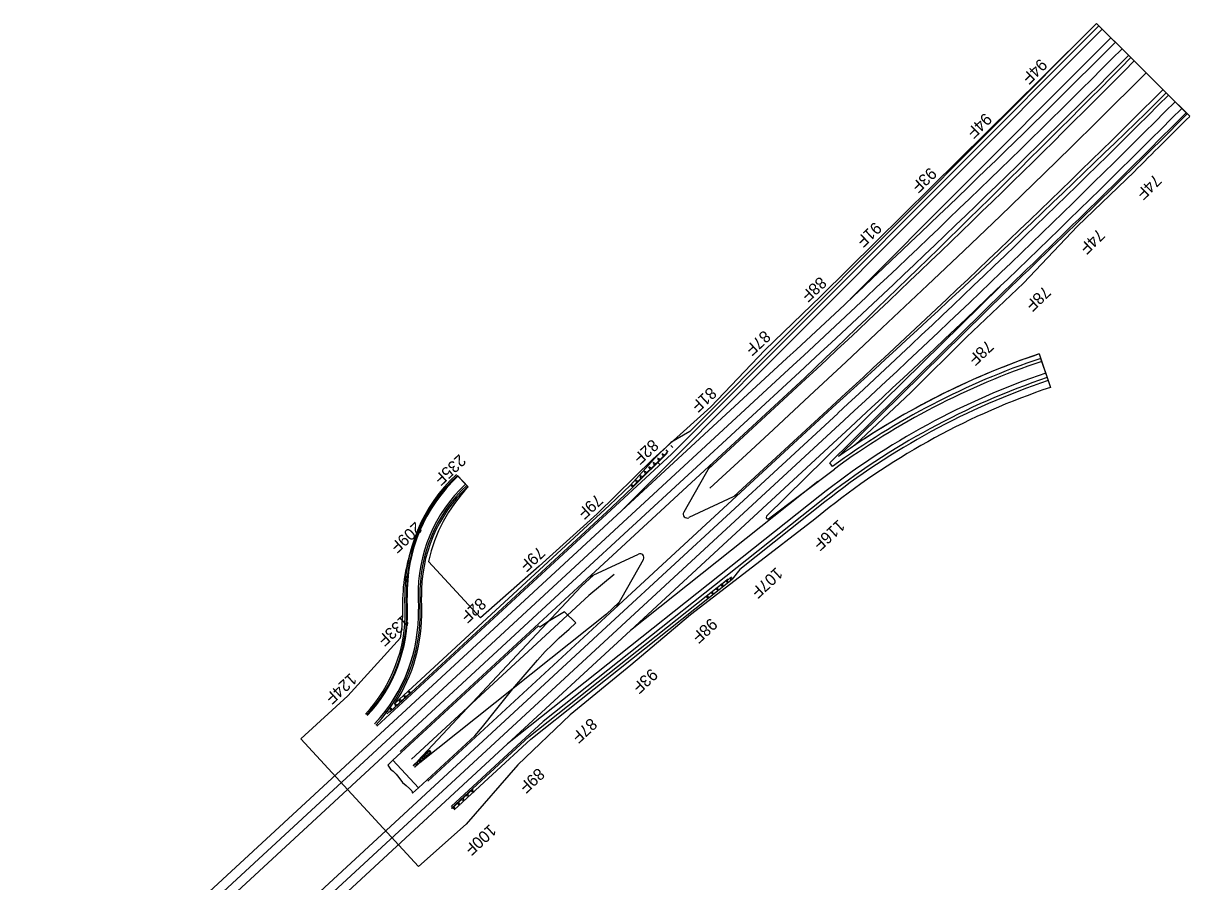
# Model space of a CAD drawing. Extents: x 2163396 to 2173129, y 605545 to 614595.
# Drawn here: x 2171635 to 2173129, y 613496 to 614595 of the extents above; entities that cross this region are included whole.
import ezdxf

# ---------------------------------------------------------------- set-up
doc = ezdxf.new("R2010")
doc.units = 0
for name, color, linetype in [('RD_PD_AsphRem', 7, 'Continuous'), ('RD_PD_CstnLmt', 7, 'Continuous'), ('RD_PD_EarthShd', 7, 'Continuous'), ('RD_PD_Final_LnLine', 7, 'Continuous'), ('RD_PD_Final_TrvlWay', 7, 'Continuous'), ('RD_PD_GR', 7, 'Continuous'), ('RD_PD_MedBWall', 7, 'Continuous'), ('RD_PD_MedGR', 7, 'Continuous'), ('RD_PD_TX_CstnLmt', 7, 'Continuous')]:
    doc.layers.add(name, color=color, linetype=linetype)

msp = doc.modelspace()

# ---------------------------------------------------------------- linework, layer by layer
at = {"layer": 'RD_PD_AsphRem'}
for p, q in [((2172295.2, 613823.7), (2172108.7, 613651.4)), ((2172213.5, 613682.8), (2172223.3, 613694.5)), ((2172141.3, 613616.1), (2172213.5, 613682.8)), ((2172108.7, 613651.4), (2172102.2, 613645.4)), ((2172102.2, 613645.4), (2172103.2, 613643.8)), ((2172108.7, 613651.4), (2172141.3, 613616.1)), ((2172141.3, 613616.1), (2172108.7, 613651.4)), ((2172133.9, 613609.3), (2172141.3, 613616.1))]:
    msp.add_line(p, q, dxfattribs=at)
for points in [[(2172223.3, 613694.5), (2172240.1, 613715.1), (2172262.5, 613742.8), (2172280.8, 613764.4), (2172294, 613779.7), (2172303.5, 613790.6), (2172312.5, 613799.5), (2172321.5, 613808.2), (2172334.3, 613819.4), (2172343, 613827.4), (2172339.4, 613831), (2172332.1, 613838.1), (2172328.5, 613841.6), (2172309.1, 613830.2), (2172296.9, 613821.9), (2172295.2, 613823.7)], [(2172103.2, 613643.8), (2172105.8, 613640.2), (2172109.2, 613637.5), (2172112.9, 613633.8), (2172116.4, 613629.4), (2172121.1, 613623.2), (2172125.8, 613619.1), (2172129.9, 613615.1), (2172132.9, 613612.2), (2172133.9, 613609.3)]]:
    msp.add_lwpolyline(points, dxfattribs=at)
at = {"layer": 'RD_PD_CstnLmt'}
for p, q in [((2173009.8, 614595.3), (2172939.6, 614525)), ((2173053.9, 614551.4), (2173009.8, 614595.3)), ((2173099.2, 614506.1), (2173053.9, 614551.4)), ((2172939.6, 614525), (2172868.8, 614455.3)), ((2173129.2, 614476.2), (2173099.2, 614506.1)), ((2172868.8, 614455.3), (2172798.1, 614385.6)), ((2173057.9, 614405.3), (2172985.6, 614335.5)), ((2172798.1, 614385.6), (2172727.4, 614315.6)), ((2172985.6, 614335.5), (2172916.4, 614262.5)), ((2172727.4, 614315.6), (2172656.9, 614245.7)), ((2172916.4, 614262.5), (2172843.4, 614193.3)), ((2172656.9, 614245.7), (2172585.1, 614176.8)), ((2172843.4, 614193.3), (2172772, 614122.4)), ((2172585.1, 614176.8), (2172515.9, 614104.3)), ((2172936.4, 614171.9), (2172950.9, 614129)), ((2172772, 614122.4), (2172700.9, 614055.5)), ((2172515.9, 614104.3), (2172441.6, 614037.3)), ((2172441.6, 614037.3), (2172370.3, 613967.2)), ((2172205.1, 614001.5), (2172191.3, 614016.2)), ((2172667.6, 613975.1), (2172649.1, 613960.1)), ((2172370.3, 613967.2), (2172296.2, 613900)), ((2172649.1, 613960.1), (2172569.4, 613899)), ((2172220.9, 613834.1), (2172154.4, 613906.2)), ((2172296.2, 613900), (2172220.9, 613834.1)), ((2172569.4, 613899), (2172489.8, 613837.7)), ((2172121.3, 613845.8), (2172121.2, 613848.3)), ((2172489.8, 613837.7), (2172413.3, 613773.2)), ((2172118.4, 613808.3), (2172051, 613733.9)), ((2172413.3, 613773.2), (2172335.8, 613709.8)), ((2172051, 613733.9), (2171990.6, 613678.8)), ((2172335.8, 613709.8), (2172268.5, 613645.8)), ((2172141.5, 613515.5), (2171990.6, 613678.8)), ((2172268.5, 613645.8), (2172202.6, 613569.7)), ((2172202.6, 613569.7), (2172141.5, 613515.5))]:
    msp.add_line(p, q, dxfattribs=at)
for centre, radius, start, end in [((2162936.5, 624645.9), 14398.4, 314.66467, 315.06467), ((2173249.3, 613242.2), 980.9, 108.5981, 123.9911), ((2173249.3, 613242.2), 935.7, 108.5981, 128.4389), ((2172335.8, 613861), 212, 132.9512, 161.6696), ((2172349.8, 613863.5), 200, 136.3428, 167.6655), ((2172333.1, 613853.5), 212, 159.524, 181.4209), ((2171933.4, 613841.2), 187.9, 349.929, 1.4209)]:
    msp.add_arc(centre, radius, start, end, dxfattribs=at)
at = {"layer": 'RD_PD_EarthShd'}
for p, q in [((2173010, 614595.1), (2172489, 614072.7)), ((2172893.3, 614251.2), (2172679.3, 614040.5)), ((2172637.7, 614139.9), (2172512.6, 614024.4)), ((2172670.3, 614104.7), (2172545.2, 613989.1)), ((2172489, 614072.7), (2172464.8, 614058.4)), ((2172443.5, 614037.4), (2172464.8, 614058.4)), ((2172443.5, 614037.4), (2172413.2, 614004)), ((2172386.2, 613978.1), (2172413.2, 614004)), ((2172111.2, 613724.2), (2172386.2, 613978.1)), ((2172661.8, 613982.3), (2172552.9, 613895.8)), ((2172365.7, 613888.7), (2172349.7, 613873.9)), ((2172552.9, 613895.8), (2172543.4, 613883.6)), ((2172349.7, 613873.9), (2172140.7, 613650.6)), ((2172285.2, 613678.6), (2172543.4, 613883.6)), ((2172124.4, 613844.7), (2172124, 613860)), ((2172145.7, 613845.3), (2172145.4, 613860.6)), ((2172398.2, 613853.4), (2172382.2, 613838.7)), ((2172382.2, 613838.7), (2172143, 613648.1)), ((2172187.1, 613588), (2172285.2, 613678.6))]:
    msp.add_line(p, q, dxfattribs=at)
for centre, radius, start, end in [((2162901.4, 624611.9), 14298.9, 312.91522, 315.26045), ((2162971.9, 624679.6), 14348.9, 312.52438, 314.86961), ((2162936.5, 624645.9), 14394, 313.76687, 315.06467), ((2173249.3, 613242.2), 980.9, 108.5981, 125.5268), ((2173249.3, 613242.2), 944.9, 108.5981, 128.4389), ((2172333, 613865.2), 209, 133.1773, 181.4209), ((2172333, 613865.2), 187.7, 133.1773, 181.4209), ((2171934.5, 613840), 190, 317.0978, 1.4209), ((2171934.5, 613840), 211.3, 326.756, 1.4209)]:
    msp.add_arc(centre, radius, start, end, dxfattribs=at)
at = {"layer": 'RD_PD_Final_LnLine'}
for p, q in [((2173017.1, 614588), (2172401.6, 613970.8)), ((2173028.4, 614576.7), (2172994.5, 614542.8)), ((2173034, 614571.1), (2173000.1, 614537.2)), ((2172994.5, 614542.8), (2172694.5, 614241.9)), ((2172886.3, 614258.4), (2172587.2, 613963.9)), ((2172621.5, 614157.6), (2172336.2, 613894.2)), ((2172401.6, 613970.8), (2172613.3, 614166.4)), ((2172629.6, 614148.7), (2172344.4, 613885.4)), ((2172678.5, 614095.8), (2172393.2, 613832.5)), ((2172686.6, 614087), (2172401.4, 613823.6)), ((2172694.7, 614078.2), (2172412.8, 613817.8)), ((2172515.9, 614030.1), (2172481.2, 613969.2)), ((2172589.8, 613960.9), (2172674.1, 614024.4)), ((2172201.6, 614005.2), (2172192, 614015.4)), ((2172653, 614008.5), (2172412.8, 613817.8)), ((2172655.6, 613990.2), (2172255.3, 613672.4)), ((2172551.1, 613991.9), (2172487.6, 613962.2)), ((2172401.6, 613970.8), (2172328.1, 613903)), ((2172359.7, 613885.9), (2172423.2, 613915.6)), ((2172328.1, 613903), (2171635.3, 613263.3)), ((2172394.9, 613847.7), (2172429.6, 613908.6)), ((2172336.2, 613894.2), (2171643.5, 613254.5)), ((2172344.4, 613885.4), (2171651.6, 613245.7)), ((2172127.4, 613844.8), (2172127, 613860.1)), ((2172141, 613860.5), (2172141.4, 613845.1)), ((2172393.2, 613832.5), (2171700.5, 613192.8)), ((2172401.4, 613823.6), (2171708.6, 613184)), ((2172412.8, 613817.8), (2172255.3, 613672.4)), ((2172085.3, 613698.3), (2172085.7, 613698.7)), ((2172255.3, 613672.4), (2171716.8, 613175.1))]:
    msp.add_line(p, q, dxfattribs=at)
for centre, radius, start, end in [((2162936.5, 624645.9), 14276, 312.71947, 315.06467), ((2162936.5, 624645.9), 14288, 312.71947, 315.06467), ((2162936.5, 624645.9), 14264, 312.71947, 314.87186), ((2162936.5, 624645.9), 14359.9, 312.71947, 315.06467), ((2162936.5, 624645.9), 14372, 312.71947, 315.06467), ((2162936.5, 624645.9), 14384, 312.71947, 315.06467), ((2173249.3, 613242.2), 970.9, 108.5981, 126.3296), ((2173249.3, 613242.2), 954.9, 108.5981, 128.4389), ((2172333, 613865.2), 206, 133.1773, 181.4209), ((2172333, 613865.2), 192, 133.1773, 181.4209), ((2172485.5, 613966.7), 5, 150.3526, 295.0863), ((2172588.6, 613962.5), 2, 134.5538, 306.9981), ((2172425.3, 613911.1), 5, 330.3526, 115.0863), ((2171934.5, 613840), 193, 317.0978, 1.4209), ((2171934.5, 613840), 207, 316.9344, 1.4209)]:
    msp.add_arc(centre, radius, start, end, dxfattribs=at)
at = {"layer": 'RD_PD_Final_TrvlWay'}
for p, q in [((2173012.8, 614592.3), (2172466, 614044)), ((2173053.9, 614551.4), (2173012.8, 614592.3)), ((2173124.7, 614480.7), (2173099.2, 614506.1)), ((2172891.9, 614252.7), (2172668.2, 614032.4)), ((2172938.3, 614166.2), (2172946.6, 614141.6)), ((2172636.4, 614141.4), (2172351.2, 613878)), ((2172671.7, 614103.2), (2172386.4, 613839.8)), ((2172466, 614044), (2172321.3, 613910.3)), ((2172671.7, 614027.6), (2172668.2, 614032.4)), ((2172659.3, 613985.5), (2172301.1, 613701.2)), ((2172321.3, 613910.3), (2172088.2, 613695.1)), ((2172351.2, 613878), (2172118.1, 613662.8)), ((2172386.4, 613839.8), (2172153.3, 613624.6)), ((2172301.1, 613701.2), (2172183.2, 613592.3))]:
    msp.add_line(p, q, dxfattribs=at)
for centre, radius, start, end in [((2157810.5, 629656.7), 21460, 313.69841, 315.26061), ((2163043.2, 624746.4), 14352.2, 312.13429, 314.47973), ((2162936.5, 624645.9), 14392, 313.76687, 315.06467), ((2173249.3, 613242.2), 974.9, 108.5981, 126.3296), ((2173249.3, 613242.2), 948.9, 108.5981, 128.4389)]:
    msp.add_arc(centre, radius, start, end, dxfattribs=at)
at = {"layer": 'RD_PD_GR'}
for p, q in [((2172461.4, 614046.2), (2172458.8, 614048.9)), ((2172467.1, 614051.9), (2172464.5, 614054.5)), ((2172458.9, 614044.5), (2172415.4, 614001.7)), ((2172415.8, 614001.3), (2172460, 614044.8)), ((2172448.6, 614038.9), (2172447.4, 614037.7)), ((2172448.9, 614037.4), (2172448, 614038.3)), ((2172448.2, 614036.8), (2172449.5, 614038)), ((2172449.6, 614035.4), (2172448.2, 614036.8)), ((2172449.5, 614038), (2172450.9, 614036.6)), ((2172450.9, 614036.6), (2172449.6, 614035.4)), ((2172454.3, 614044.5), (2172453.1, 614043.3)), ((2172454.6, 614043), (2172453.7, 614043.9)), ((2172453.9, 614042.4), (2172455.2, 614043.6)), ((2172455.3, 614041), (2172453.9, 614042.4)), ((2172455.2, 614043.6), (2172456.6, 614042.2)), ((2172456.6, 614042.2), (2172455.3, 614041)), ((2172459.3, 614045.6), (2172458.6, 614044.9)), ((2172458.6, 614044.9), (2172458.9, 614044.5)), ((2172460, 614044.8), (2172459.3, 614045.6)), ((2172431.5, 614022.1), (2172430.3, 614020.9)), ((2172431.8, 614020.6), (2172430.9, 614021.5)), ((2172431.1, 614020), (2172432.4, 614021.2)), ((2172432.5, 614018.5), (2172431.1, 614020)), ((2172432.4, 614021.2), (2172433.8, 614019.8)), ((2172433.8, 614019.8), (2172432.5, 614018.5)), ((2172437.2, 614027.7), (2172436, 614026.5)), ((2172437.5, 614026.2), (2172436.6, 614027.1)), ((2172436.8, 614025.6), (2172438.1, 614026.8)), ((2172438.2, 614024.2), (2172436.8, 614025.6)), ((2172438.1, 614026.8), (2172439.5, 614025.4)), ((2172439.5, 614025.4), (2172438.2, 614024.2)), ((2172442.9, 614033.3), (2172441.7, 614032.1)), ((2172443.2, 614031.8), (2172442.3, 614032.7)), ((2172442.5, 614031.2), (2172443.8, 614032.4)), ((2172443.9, 614029.8), (2172442.5, 614031.2)), ((2172443.8, 614032.4), (2172445.2, 614031)), ((2172445.2, 614031), (2172443.9, 614029.8)), ((2172450.5, 614030.2), (2172447.9, 614032.9)), ((2172414.4, 614005.2), (2172413.2, 614004)), ((2172414.7, 614003.7), (2172413.8, 614004.6)), ((2172414, 614003.1), (2172415.3, 614004.3)), ((2172415.3, 614004.3), (2172416.7, 614002.9)), ((2172420.1, 614010.9), (2172418.9, 614009.6)), ((2172420.4, 614009.3), (2172419.5, 614010.2)), ((2172419.7, 614008.7), (2172421, 614010)), ((2172421.1, 614007.3), (2172419.7, 614008.7)), ((2172421, 614010), (2172422.4, 614008.5)), ((2172422.4, 614008.5), (2172421.1, 614007.3)), ((2172425.8, 614016.5), (2172424.6, 614015.2)), ((2172426.1, 614015), (2172425.2, 614015.9)), ((2172425.4, 614014.3), (2172426.7, 614015.6)), ((2172426.8, 614012.9), (2172425.4, 614014.3)), ((2172426.7, 614015.6), (2172428.1, 614014.2)), ((2172428.1, 614014.2), (2172426.8, 614012.9)), ((2172388.8, 613975.4), (2172415.8, 614001.3)), ((2172415.4, 614001.7), (2172414, 614003.1)), ((2172416.7, 614002.9), (2172415.4, 614001.7)), ((2172415.4, 614001.7), (2172415.8, 614001.3)), ((2172131.6, 613737.9), (2172388.8, 613975.4)), ((2172392, 613889.6), (2172359.8, 613862.5)), ((2172539.5, 613885.3), (2172541.9, 613882.3)), ((2172541.1, 613886.5), (2172543.4, 613883.6)), ((2172509.8, 613861.6), (2172538, 613884)), ((2172537.5, 613883), (2172510.1, 613861.3)), ((2172524, 613872.3), (2172522.6, 613871.2)), ((2172522.6, 613871.2), (2172523.9, 613869.6)), ((2172523.9, 613869.6), (2172525.2, 613870.7)), ((2172525.2, 613870.7), (2172524, 613872.3)), ((2172524.5, 613870.2), (2172525.3, 613869.2)), ((2172526, 613869.7), (2172524.6, 613868.7)), ((2172530.3, 613877.3), (2172528.9, 613876.2)), ((2172528.9, 613876.2), (2172530.1, 613874.6)), ((2172530.1, 613874.6), (2172531.5, 613875.7)), ((2172531.5, 613875.7), (2172530.3, 613877.3)), ((2172530.8, 613875.2), (2172531.6, 613874.2)), ((2172532.3, 613874.7), (2172530.9, 613873.6)), ((2172536.5, 613882.2), (2172535.2, 613881.1)), ((2172535.2, 613881.1), (2172536.4, 613879.6)), ((2172536.4, 613879.6), (2172537.8, 613880.7)), ((2172537.8, 613880.7), (2172536.5, 613882.2)), ((2172537.1, 613880.1), (2172537.9, 613879.1)), ((2172538.5, 613879.7), (2172537.2, 613878.6)), ((2172537.8, 613882.6), (2172537.5, 613883)), ((2172538.6, 613883.2), (2172537.8, 613882.6)), ((2172538, 613884), (2172538.6, 613883.2)), ((2172359.8, 613862.5), (2172132.6, 613652.7)), ((2172282.8, 613681.5), (2172509.8, 613861.6)), ((2172510.1, 613861.3), (2172509.8, 613861.6)), ((2172511.5, 613862.3), (2172510.1, 613861.3)), ((2172510.1, 613861.3), (2172511.3, 613859.7)), ((2172511.3, 613859.7), (2172512.7, 613860.8)), ((2172512.7, 613860.8), (2172511.5, 613862.3)), ((2172512, 613860.2), (2172512.8, 613859.3)), ((2172513.5, 613859.8), (2172512.1, 613858.7)), ((2172517.7, 613867.3), (2172516.4, 613866.2)), ((2172516.4, 613866.2), (2172517.6, 613864.7)), ((2172517.6, 613864.7), (2172519, 613865.7)), ((2172519, 613865.7), (2172517.7, 613867.3)), ((2172518.3, 613865.2), (2172519.1, 613864.2)), ((2172519.7, 613864.8), (2172518.4, 613863.7)), ((2172131.6, 613737.9), (2172105.2, 613713.5)), ((2172105.6, 613714.5), (2172131.3, 613738.3)), ((2172121.9, 613734), (2172123.2, 613735.2)), ((2172127.8, 613739.5), (2172129.1, 613740.7)), ((2172129.3, 613739.1), (2172128.4, 613740.1)), ((2172129.9, 613739.7), (2172128.6, 613738.6)), ((2172128.6, 613738.6), (2172130, 613737.1)), ((2172131.3, 613738.3), (2172129.9, 613739.7)), ((2172130, 613737.1), (2172131.3, 613738.3)), ((2172131.3, 613738.3), (2172131.6, 613737.9)), ((2172110.2, 613723.2), (2172111.4, 613724.4)), ((2172111.7, 613722.9), (2172110.8, 613723.8)), ((2172112.3, 613723.5), (2172111, 613722.3)), ((2172111, 613722.3), (2172112.4, 613720.8)), ((2172113.7, 613722), (2172112.3, 613723.5)), ((2172112.4, 613720.8), (2172113.7, 613722)), ((2172116, 613728.6), (2172117.3, 613729.8)), ((2172117.5, 613728.3), (2172116.7, 613729.2)), ((2172118.2, 613728.9), (2172116.9, 613727.7)), ((2172116.9, 613727.7), (2172118.2, 613726.2)), ((2172119.5, 613727.4), (2172118.2, 613728.9)), ((2172118.2, 613726.2), (2172119.5, 613727.4)), ((2172123.4, 613733.7), (2172122.6, 613734.6)), ((2172124.1, 613734.3), (2172122.8, 613733.1)), ((2172122.8, 613733.1), (2172124.1, 613731.7)), ((2172125.4, 613732.8), (2172124.1, 613734.3)), ((2172124.1, 613731.7), (2172125.4, 613732.8)), ((2172102.2, 613710.8), (2172099.7, 613713.5)), ((2172103.7, 613712.1), (2172101.2, 613714.9)), ((2172104.3, 613717.8), (2172105.6, 613719)), ((2172104.5, 613714.2), (2172105.2, 613714.9)), ((2172105.2, 613713.5), (2172104.5, 613714.2)), ((2172105.8, 613717.4), (2172104.9, 613718.4)), ((2172106.4, 613718), (2172105.1, 613716.8)), ((2172105.1, 613716.8), (2172106.5, 613715.4)), ((2172105.2, 613714.9), (2172105.6, 613714.5)), ((2172107.8, 613716.6), (2172106.4, 613718)), ((2172106.5, 613715.4), (2172107.8, 613716.6)), ((2172211, 613615.2), (2172282.8, 613681.5)), ((2172211, 613615.2), (2172183.8, 613590.1)), ((2172184.2, 613589.7), (2172211.3, 613614.8)), ((2172197, 613601.6), (2172198.3, 613602.8)), ((2172198.4, 613600.1), (2172197, 613601.6)), ((2172198.3, 613602.8), (2172199.6, 613601.3)), ((2172199.6, 613601.3), (2172198.4, 613600.1)), ((2172199, 613600.7), (2172199.8, 613599.8)), ((2172199.2, 613599.2), (2172200.5, 613600.4)), ((2172202.9, 613607), (2172204.2, 613608.2)), ((2172204.2, 613605.5), (2172202.9, 613607)), ((2172204.2, 613608.2), (2172205.5, 613606.7)), ((2172205.5, 613606.7), (2172204.2, 613605.5)), ((2172204.9, 613606.1), (2172205.7, 613605.2)), ((2172205.1, 613604.6), (2172206.4, 613605.8)), ((2172208.8, 613612.4), (2172210, 613613.6)), ((2172210.1, 613611), (2172208.8, 613612.4)), ((2172210, 613613.6), (2172211.4, 613612.2)), ((2172211.4, 613612.2), (2172210.1, 613611)), ((2172210.8, 613611.6), (2172211.6, 613610.7)), ((2172211.3, 613614.8), (2172211, 613615.2)), ((2172211, 613610.1), (2172212.2, 613611.2)), ((2172183.8, 613590.1), (2172184.2, 613589.7)), ((2172185.2, 613590.7), (2172186.5, 613591.9)), ((2172186.6, 613589.3), (2172185.2, 613590.7)), ((2172186.5, 613591.9), (2172187.9, 613590.5)), ((2172187.9, 613590.5), (2172186.6, 613589.3)), ((2172187.2, 613589.9), (2172188.1, 613588.9)), ((2172187.4, 613588.3), (2172188.7, 613589.5)), ((2172188.8, 613594), (2172188.5, 613594.4)), ((2172191.1, 613596.2), (2172192.4, 613597.4)), ((2172192.5, 613594.7), (2172191.1, 613596.2)), ((2172192.4, 613597.4), (2172193.8, 613595.9)), ((2172193.8, 613595.9), (2172192.5, 613594.7)), ((2172193.1, 613595.3), (2172194, 613594.4)), ((2172193.3, 613593.8), (2172194.6, 613595))]:
    msp.add_line(p, q, dxfattribs=at)
msp.add_lwpolyline([(2172514.8, 613999.9), (2172561.6, 614043.2), (2172596.1, 614075.2), (2172642.4, 614118.3), (2172689.1, 614161.9), (2172735.2, 614205.2), (2172793.6, 614259.9), (2172840, 614304), (2172886.9, 614348.7), (2172942.8, 614403), (2172977.3, 614436.7), (2173011.8, 614470.8), (2173073.3, 614531.9)], dxfattribs=at)
at = {"layer": 'RD_PD_MedBWall'}
for p, q in [((2172192, 614015.4), (2172191.3, 614016.2)), ((2172203.2, 614003.5), (2172201.6, 614005.2)), ((2172126.4, 613844.8), (2172126, 613860.1)), ((2172141, 613860.5), (2172141.4, 613845.1)), ((2172143.7, 613845.2), (2172143.4, 613860.5)), ((2172087.3, 613697), (2172086.9, 613696.6))]:
    msp.add_line(p, q, dxfattribs=at)
for centre, radius, start, end in [((2172333, 613865.2), 207, 133.1773, 181.4209), ((2172333, 613865.2), 192, 133.1773, 181.4209), ((2172333, 613865.2), 189.7, 133.1773, 181.4209), ((2171934.5, 613840), 192, 317.0978, 1.4209), ((2171934.5, 613840), 207, 317.0978, 1.4209), ((2171934.5, 613840), 209.3, 316.9104, 1.4209)]:
    msp.add_arc(centre, radius, start, end, dxfattribs=at)
at = {"layer": 'RD_PD_MedGR'}
for p, q in [((2172134.6, 613644.9), (2172154.4, 613663.2)), ((2172134.6, 613644.9), (2172154.4, 613663.2)), ((2172136.8, 613642.5), (2172156.7, 613660.8)), ((2172156.7, 613660.8), (2172136.8, 613642.5)), ((2172137.9, 613647.2), (2172154.8, 613662.9)), ((2172139.4, 613645.5), (2172156.3, 613661.1)), ((2172152.6, 613660.8), (2172150.6, 613659.1)), ((2172154.1, 613659.1), (2172152.6, 613660.8)), ((2172154.4, 613659.4), (2172152.8, 613661.1)), ((2172156.7, 613660.8), (2172154.4, 613663.2)), ((2172154.7, 613662.9), (2172154.4, 613663.2)), ((2172156.7, 613660.8), (2172156.4, 613661.1)), ((2172134.9, 613644.5), (2172137.9, 613647.2)), ((2172137.9, 613647.2), (2172134.9, 613644.5)), ((2172136.5, 613642.8), (2172139.4, 613645.5)), ((2172136.5, 613642.8), (2172139.4, 613645.5)), ((2172139.3, 613648.6), (2172137.9, 613647.2)), ((2172139.4, 613645.5), (2172137.9, 613647.2)), ((2172139.6, 613648.9), (2172139.3, 613648.6)), ((2172140.9, 613646.9), (2172139.3, 613648.6)), ((2172141.5, 613650.6), (2172139.6, 613648.9)), ((2172141.2, 613647.2), (2172139.6, 613648.9)), ((2172141.8, 613650.9), (2172141.5, 613650.6)), ((2172143.1, 613648.9), (2172141.5, 613650.6)), ((2172143.7, 613652.7), (2172141.8, 613650.9)), ((2172143.4, 613649.2), (2172141.8, 613650.9)), ((2172144, 613652.9), (2172143.7, 613652.7)), ((2172145.3, 613651), (2172143.7, 613652.7)), ((2172145.9, 613654.7), (2172144, 613652.9)), ((2172145.6, 613651.2), (2172144, 613652.9)), ((2172146.2, 613655), (2172145.9, 613654.7)), ((2172147.5, 613653), (2172145.9, 613654.7)), ((2172148.1, 613656.7), (2172146.2, 613655)), ((2172147.8, 613653.3), (2172146.2, 613655)), ((2172148.4, 613657), (2172148.1, 613656.7)), ((2172149.7, 613655), (2172148.1, 613656.7)), ((2172150.3, 613658.8), (2172148.4, 613657)), ((2172150, 613655.3), (2172148.4, 613657)), ((2172150.6, 613659.1), (2172150.3, 613658.8)), ((2172151.9, 613657.1), (2172150.3, 613658.8)), ((2172152.2, 613657.3), (2172150.6, 613659.1)), ((2172134.6, 613644.9), (2172134.9, 613644.5)), ((2172134.9, 613644.5), (2172134.6, 613644.9)), ((2172136.8, 613642.5), (2172136.5, 613642.8)), ((2172136.8, 613642.5), (2172136.5, 613642.8))]:
    msp.add_line(p, q, dxfattribs=at)
for points in [[(2172139.4, 613645.5), (2172140.9, 613646.9), (2172141.2, 613647.2), (2172143.1, 613648.9), (2172143.4, 613649.2), (2172145.3, 613651), (2172145.6, 613651.2), (2172147.5, 613653), (2172147.8, 613653.3), (2172149.7, 613655), (2172150, 613655.3), (2172151.9, 613657.1), (2172152.2, 613657.3), (2172154.1, 613659.1), (2172154.4, 613659.4), (2172156.3, 613661.1)], [(2172154.8, 613662.9), (2172152.8, 613661.1), (2172152.6, 613660.8)], [(2172154.4, 613663.2), (2172154.7, 613662.9), (2172154.8, 613662.9)], [(2172156.3, 613661.1), (2172156.4, 613661.1), (2172156.7, 613660.8)]]:
    msp.add_lwpolyline(points, dxfattribs=at)
for radius in [1.67, 1.67, 1.27, 1.27]:
    msp.add_arc((2172155.5, 613662), radius, 312.7195, 132.7195, dxfattribs=at)

# ---------------------------------------------------------------- texts
at = {"layer": 'RD_PD_TX_CstnLmt'}
for s, rotation, p in [('94F', 224.6647, (2172937.7, 614551.1)), ('94F', 224.2647, (2172867, 614481.5)), ('93F', 223.8647, (2172796.4, 614411.8)), ('74F', 224.6647, (2173084.1, 614403)), ('91F', 223.4647, (2172726, 614341.9)), ('74F', 224.2647, (2173011.7, 614333.1)), ('88F', 223.0647, (2172655.6, 614271.9)), ('78F', 223.8647, (2172942.5, 614259.8)), ('87F', 222.7195, (2172584, 614203)), ('78F', 223.4647, (2172869.5, 614190.5)), ('81F', 222.7195, (2172514.8, 614130.5)), ('82F', 222.7195, (2172440.5, 614063.6)), ('235F', 222.7195, (2172193.8, 614044.3)), ('79F', 222.7195, (2172369.2, 613993.4)), ('116F', 222.7195, (2172679.3, 613960.7)), ('209F', 222.7195, (2172137.6, 613957.7)), ('79F', 222.7195, (2172295.1, 613926.2)), ('107F', 222.7195, (2172599.6, 613899.6)), ('82F', 222.7195, (2172219.6, 613860.6)), ('133F', 222.7195, (2172121.5, 613838.4)), ('98F', 222.7195, (2172515.8, 613834.6)), ('93F', 222.7195, (2172439.4, 613770)), ('124F', 222.7195, (2172054.1, 613764)), ('87F', 222.7195, (2172361.8, 613706.6)), ('89F', 222.7195, (2172294.6, 613642.6)), ('100F', 222.7195, (2172232.8, 613570.4))]:
    msp.add_text(s, height=15, rotation=rotation, dxfattribs=at).set_placement(p)

doc.saveas('drawing.dxf')
